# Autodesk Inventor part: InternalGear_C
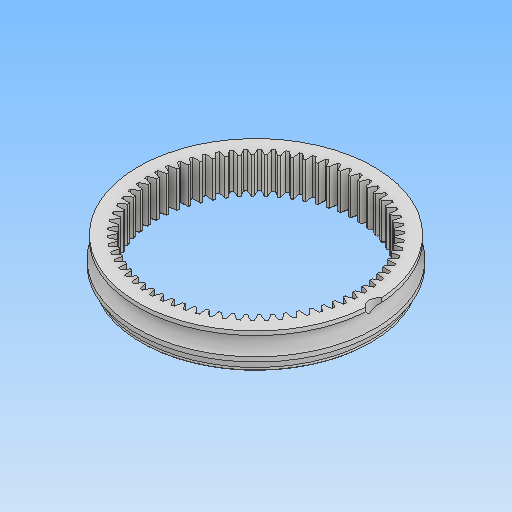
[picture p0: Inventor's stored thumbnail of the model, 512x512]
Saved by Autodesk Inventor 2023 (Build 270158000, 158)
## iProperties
Created: 2024-05
Part Number: InternalGear_C
Material: 一般
Document SubType Name: Modeling
Designer: kumagai
Density: 1 g/cm^3
Appearance: 既定
Author: kumagai
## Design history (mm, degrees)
derived "InternalGear.iam"
chamfer "面取り1" distance "d1" = 0.3; stored, may be unused: second distance "d2" = 2, angle "d3" = 45 deg
node "ソリッド1"
node "InternalGearRace.ipt:1" dims "d0" = 10
node "平歯車2:1" dims "d0" = 10
